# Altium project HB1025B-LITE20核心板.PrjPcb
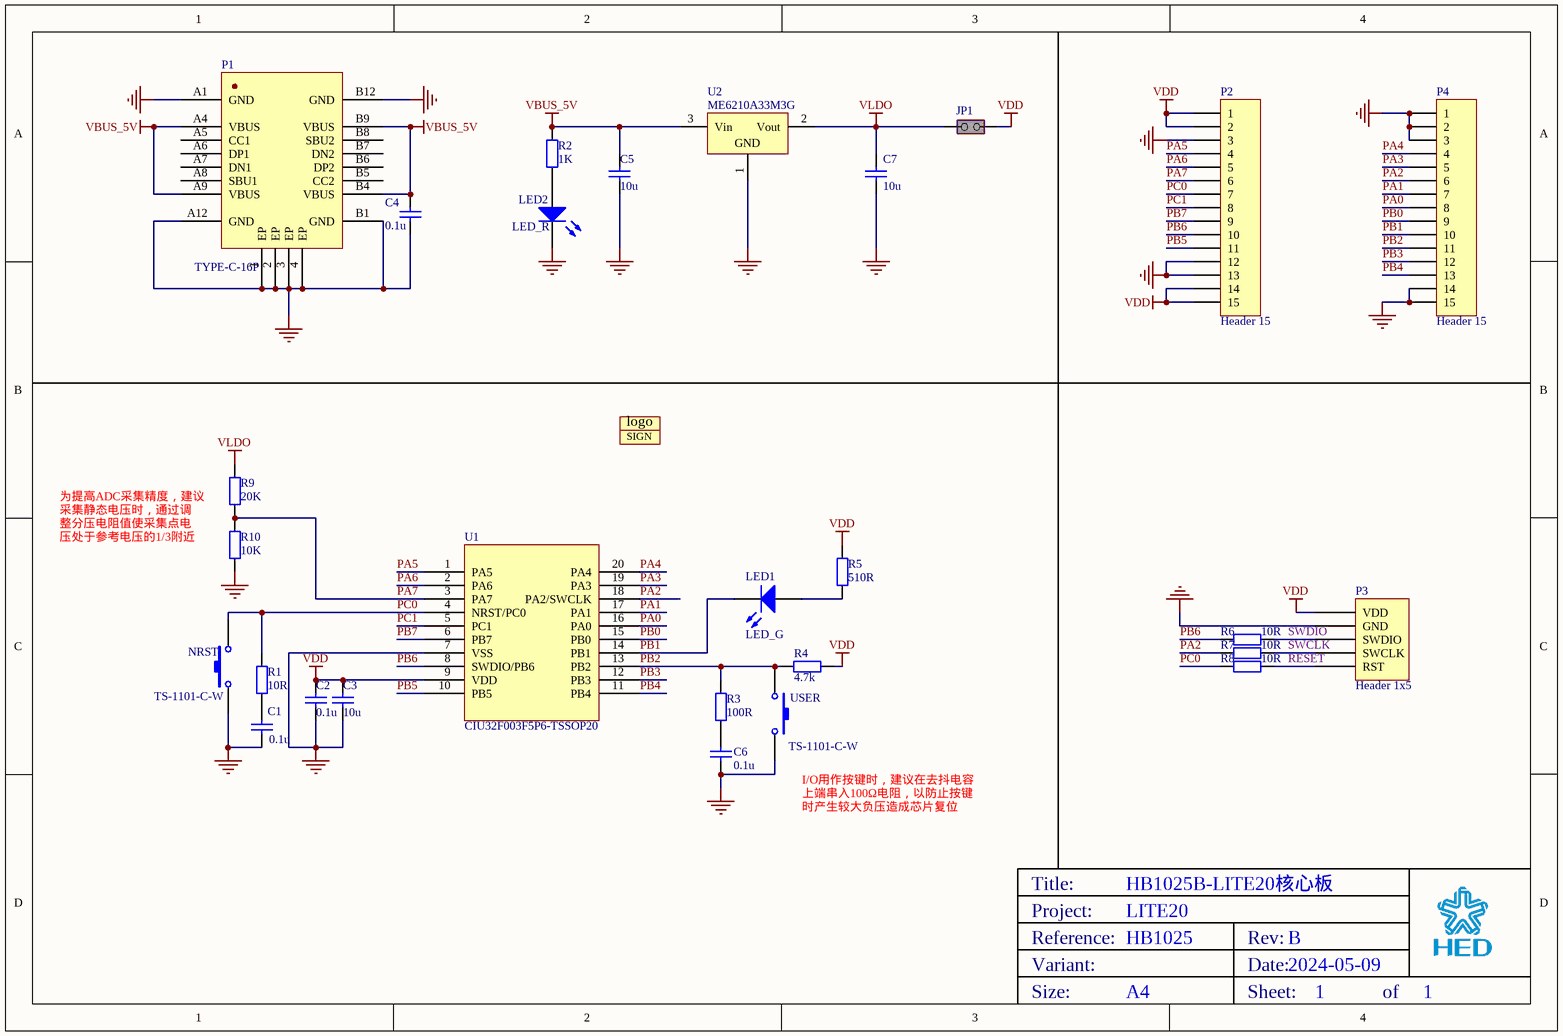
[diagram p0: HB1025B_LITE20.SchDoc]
Board_Assembly_Revision: 01; Board_Name: LITE20; Board_PCB_Revision: B; Board_Reference: HB1025
1 sheet, 30 parts. Net scope: global (net labels, ports and power ports of the same name join across sheets).
Board file: HB1025B.PcbDoc

## Sheet HB1025B_LITE20.SchDoc: HB1025B-LITE20核心板
size A4; Date: 2024-05-09; SheetNumber: 1; SheetTotal: 1

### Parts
C1  0.1u  [0402]
C2  0.1u  [0402]
C3  10u  [0402]
C4  0.1u  [0402]
C5  10u  [0402]
C6  0.1u  [0402]
C7  10u  [0402]
JP1  Header 1x2  [HEADER_1X2_2.54]  (value not drawn)
LED1  LED_G  [0603-P]
LED2  LED_R  [0603-P]
logo1  logo  [LOGO]  (value not drawn)
logo2  SIGN  [SIGN]  (value not drawn)
NRST  TS-1101-C-W  [按键_TS-1101-C-W]
P1  TYPE-C-16P  [HED-KH-TYPE-C-16P]
P2  Header 15  [HDR1X15]
P3  Header 1x5  [HDR1X5_2.54]
P4  Header 15  [HDR1X15]
R1  10R  [0402]
R2  1K  [0402]
R3  100R  [0402]
R4  4.7k  [0402]
R5  510R  [0402]
R6  10R  [0402]
R7  10R  [0402]
R8  10R  [0402]
R9  20K  [0402]
R10  10K  [0402]
U1  CIU32F003F5P6-TSSOP20  [CIU32F003-TSSOP-20N]
U2  ME6210A33M3G  [SOT-23-3]
USER  TS-1101-C-W  [按键_TS-1101-C-W]

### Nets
GND: C1.2 C2.2 C3.2 C4.1 C5.1 C6.1 C7.1 LED2.2(K) NRST.1 P1.1(EP) P1.2(EP) P1.3(EP) P1.4(EP) P1.A1(GND) P1.A12(GND) P1.B1(GND) P1.B12(GND) P2.3 P2.12 P2.13 P3.2(GND) P4.1 P4.2 P4.3 P4.14 P4.15 R10.2 U1.7(VSS) U2.1(GND) USER.1
VBUS_5V: C4.2 C5.2 P1.A4(VBUS) P1.A9(VBUS) P1.B4(VBUS) P1.B9(VBUS) R2.2 U2.3(Vin)
VDD: C2.1 C3.1 JP1.1(COMMON) P2.1 P2.2 P2.14 P2.15 P3.1(VDD) R4.2 R5.2 U1.9(VDD)
VLDO: C7.2 JP1.2(NO) R9.2 U2.2(Vout)
PA0: P4.8 U1.16(PA0)
PA1: P4.7 U1.17(PA1)
PA2: P4.6 R7.1 U1.18(PA2/SWCLK)
PA3: P4.5 U1.19(PA3)
PA4: P4.4 U1.20(PA4)
PA5: P2.4 U1.1(PA5)
PA6: P2.5 U1.2(PA6)
PA7: P2.6 R9.1 R10.1 U1.3(PA7)
PB0: P4.9 U1.15(PB0)
PB1: LED1.2(K) P4.10 U1.14(PB1)
PB2: P4.11 R3.2 R4.1 U1.13(PB2) USER.2
PB3: P4.12 U1.12(PB3)
PB4: P4.13 U1.11(PB4)
PB5: P2.11 U1.10(PB5)
PB6: P2.10 R6.1 U1.8(SWDIO/PB6)
PB7: P2.9 U1.6(PB7)
PC0: NRST.2 P2.7 R1.1 R8.1 U1.4(NRST/PC0)
PC1: P2.8 U1.5(PC1)
RESET: P3.5(RST) R8.2
SWCLK: P3.4(SWCLK) R7.2
SWDIO: P3.3(SWDIO) R6.2
NetC1_1: C1.1 R1.2
NetC6_2: C6.2 R3.1
NetLED1_1: LED1.1(A) R5.1
NetLED2_1: LED2.1(A) R2.1

Not connected (* = marked no-connect by the designer): P1 A5(CC1) A6(DP1) A7(DN1) A8(SBU1) B5(CC2) B6(DP2) B7(DN2) B8(SBU2)

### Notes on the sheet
- 为提高ADC采集精度，建议
- 采集静态电压时，通过调
- 整分压电阻值使采集点电
- 压处于参考电压的1/3附近
- (near USER) I/O用作按键时，建议在去抖电容
- 上端串入100Ω电阻，以防止按键
- 时产生较大负压造成芯片复位

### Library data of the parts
C1-C3 = MCD-00211: Capacitor, MLCC, 100nF, 16V, X7R, 10%, 0603, T=0,8mm; Manufacturer_Part_Number: CC0603KRX7R7BB104; Manufacturer: YAGEO; Provided_By: Subcon; Initial_Board_Reference: mb1319
C4 = 0603 100nF 10% 50V: 贴片电容
C5 C7 = MCD-00014: Capacitor, MLCC, 10uF, 25V, X5R, 10%, 0805, T=0,85mm; Manufacturer_Part_Number: CC0805KRX5R8BB106; Manufacturer: YAGEO; Provided_By: Subcon; Initial_Board_Reference: mb1274
C6 = MCD-00211: 贴片电容; Manufacturer_Part_Number: CC0603KRX7R7BB104; Manufacturer: YAGEO; Provided_By: Subcon; Initial_Board_Reference: mb1319
JP1 = MCD-00683: Header, 2x1, 2,54mm, VR, TH, Height 5.84mm/2.54mm - Shunt Fitted by default; Part_Type: Connector; Manufacturer_Part_Number: TSW-102-07-x-S; Manufacturer: SAMTEC; Provided_By: Subcon; Initial_Board_Reference: MB1331
LED1 = LED1: 贴片LED 绿色
LED2 = LED1: 贴片LED 红色
NRST = SW-PB: Switch
P1 = KH-TYPE-C-16P: TYPE-C USB接口
P2 P4 = Header 15: Header, 15-Pin
P3 = SWD: Header, 1x5, 2,54mm, VR, TH, Height 5.84mm/2.54mm
R1 R3-R8 = Res2: 贴片电阻; Value: 1K
R2 = Res2: 贴片电阻
R9 R10 = Res2: 贴片电阻; Value: 47K
U2 = ME6210: 贴片LDO3.3V; Manufacturer: 微盟电子
USER = SW-PB: 贴片按键

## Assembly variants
None: all parts fitted
Default: all parts fitted
HB1025A_BOM: all parts fitted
